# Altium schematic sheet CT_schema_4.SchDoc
size 312 x 277 mm
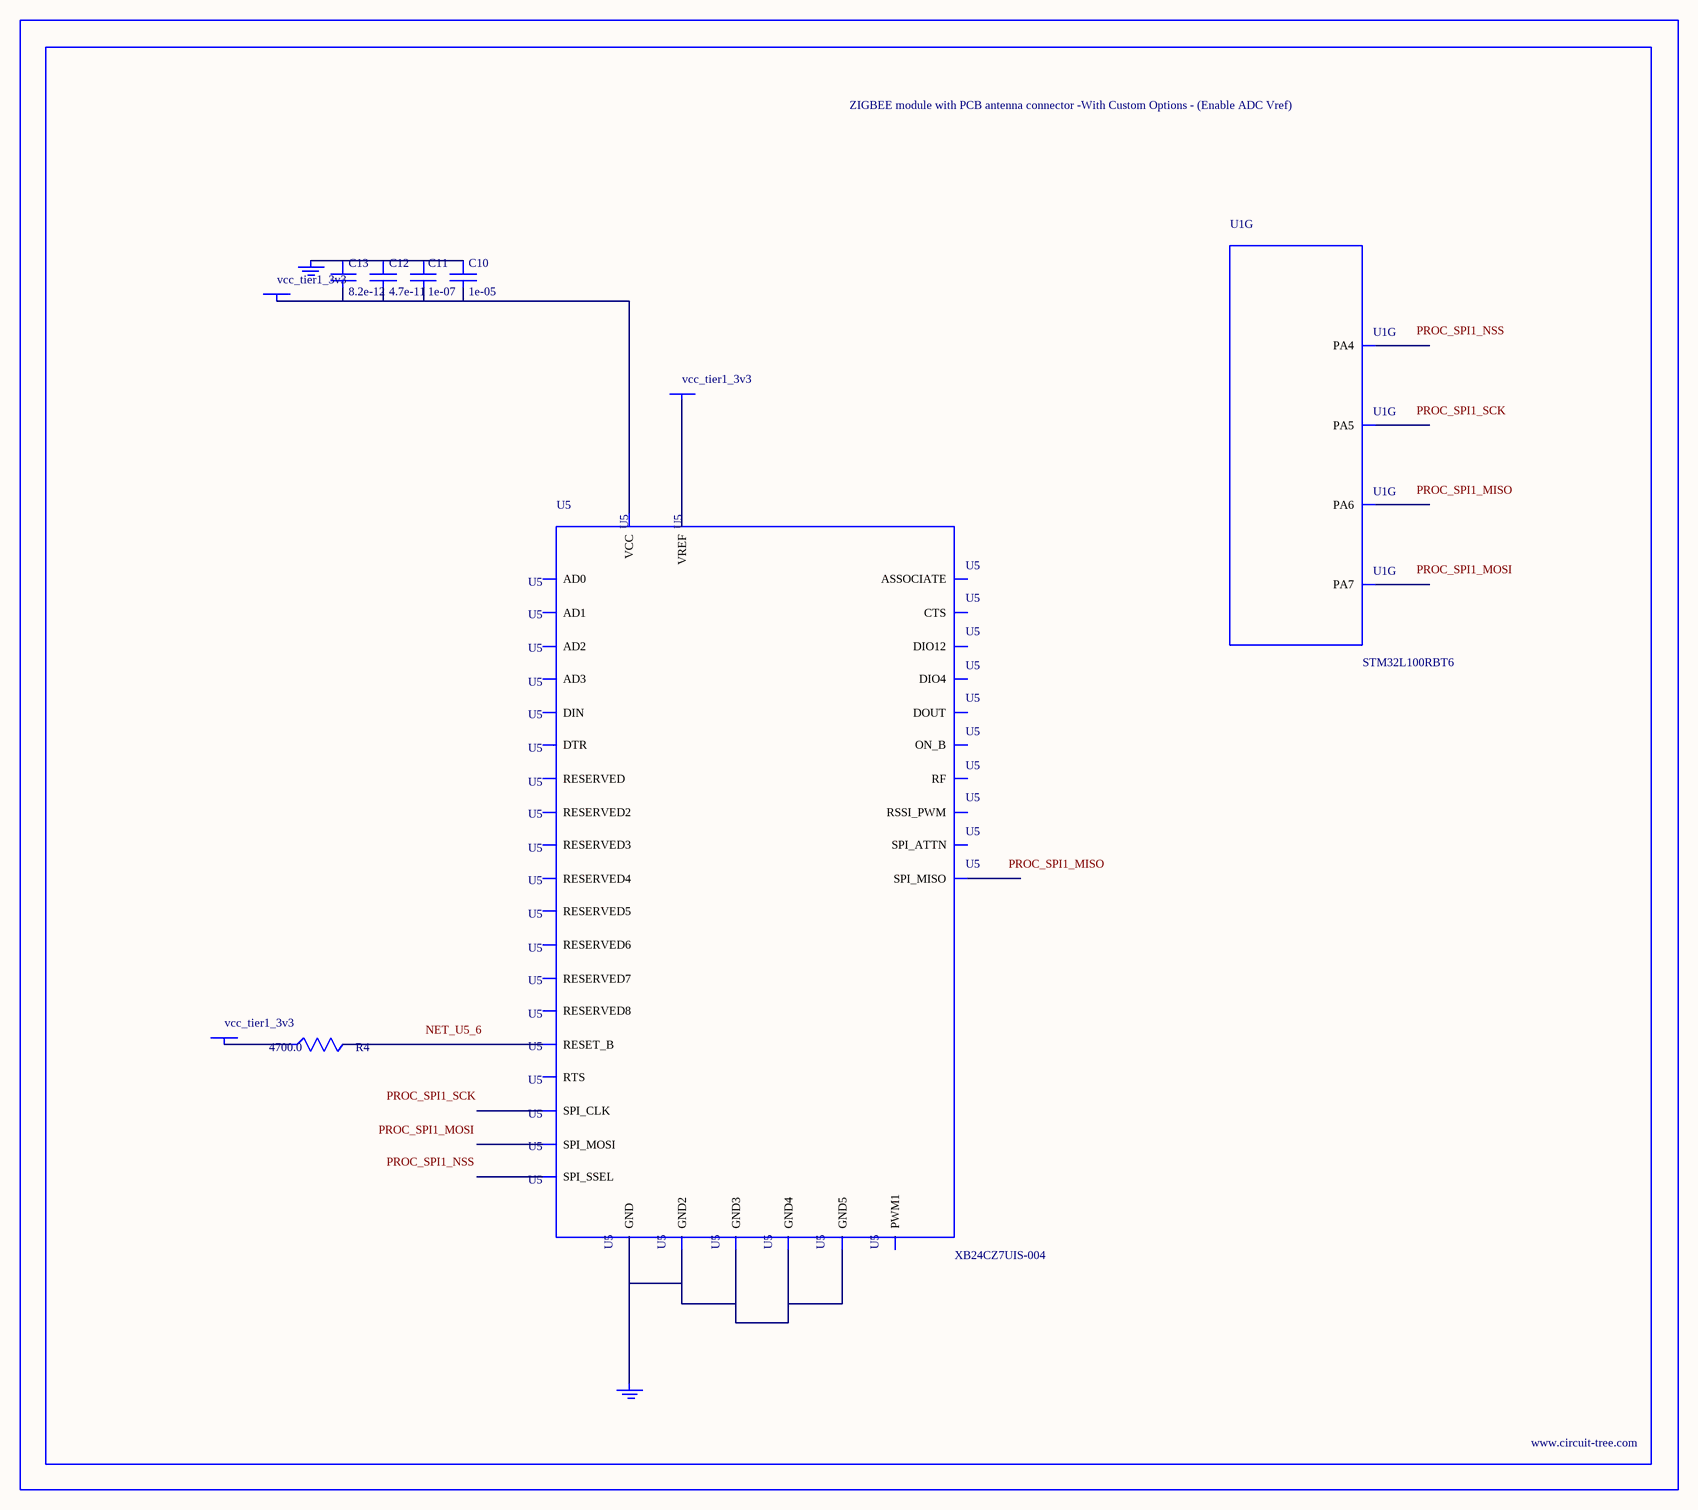
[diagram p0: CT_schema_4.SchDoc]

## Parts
BORDER3  (no value)
C10  1e-05  [C0805]
C11  1e-07  [C0402]
C12  4.7e-11  [C0402]
C13  8.2e-12  [C0603]
GND_INSTANCE_3_0  (no value)
GND_INSTANCE_3_1  (no value)
POWER_INSTANCE_3_0  vcc_tier1_3v3
POWER_INSTANCE_3_1  vcc_tier1_3v3
POWER_INSTANCE_3_2  vcc_tier1_3v3
R4  4700.0  [R0603]
U1  STM32L100RBT6  [LQFP64]  (part G of 7)
U5  XB24CZ7UIS-004  [XB24CZ7UIS-004]

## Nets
NetC10_1: C10.1 C11.1 C12.1 C13.1 GND_INSTANCE_3_0.0(GND)
NetC10_2: C10.2 C11.2 C12.2 C13.2 POWER_INSTANCE_3_0.0(PWR) U5.2(VCC)
NetGND_INSTANCE_3_1_0: GND_INSTANCE_3_1.0(GND) U5.1(GND) U5.11(GND2) U5.13(GND3) U5.22(GND4) U5.35(GND5)
NetPOWER_INSTANCE_3_1_0: POWER_INSTANCE_3_1.0(PWR) R4.1
NetPOWER_INSTANCE_3_2_0: POWER_INSTANCE_3_2.0(PWR) U5.27(VREF)
NetR4_2: R4.2 U5.6(RESET_B)

Not connected (* = marked no-connect by the designer): U1 20(PA4) 21(PA5) 22(PA6) 23(PA7); U5 3(DOUT) 4(DIN) 5(DIO12) 7(RSSI_PWM) 8(PWM1) 9(RESERVED) 10(DTR) 12(SPI_ATTN) 14(SPI_CLK) 15(SPI_SSEL) 16(SPI_MOSI) 17(SPI_MISO) 18(RESERVED2) 19(RESERVED3) 20(RESERVED4) 21(RESERVED5) 23(RESERVED6) 24(DIO4) 25(CTS) 26(ON_B) 28(ASSOCIATE) 29(RTS) 30(AD3) 31(AD2) 32(AD1) 33(AD0) 34(RESERVED7) 36(RF) 37(RESERVED8)

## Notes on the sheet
- Labels drawn without touching a wire or pin: NET_U5_6, PROC_SPI1_MISO, PROC_SPI1_MOSI, PROC_SPI1_NSS, PROC_SPI1_SCK

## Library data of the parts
BORDER3 = BORDER_PAGE3
C10 = C0805C106K8RACTU
C11 = C0402C104K3RACTU
C12 = C0402C470K3RAC
C13 = 06035J8R2BBTTR
GND_INSTANCE_3_0 GND_INSTANCE_3_1 = GND
POWER_INSTANCE_3_0-POWER_INSTANCE_3_2 = PWR
R4 = RC0603JR-074K7L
